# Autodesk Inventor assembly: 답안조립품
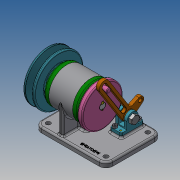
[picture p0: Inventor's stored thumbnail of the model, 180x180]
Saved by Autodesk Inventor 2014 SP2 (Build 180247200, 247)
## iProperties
Created: 2019-09
Part Number: 답안조립품
Document SubType Name: Assembly
Designer: kb542
Mass: 1417.85 g
Surface Area: 1426.65 cm^2
Volume: 427.118 cm^3
Density: 3.31959 g/cm^3
Author: kb542
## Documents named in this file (19)
- C:\Users\kb542\Desktop\390904V1007\답안조립품.iam
- C:\Users\kb542\Desktop\390904V1007\본체.ipt
- C:\Users\kb542\Desktop\390904V1007\V-벨트풀리.ipt
- C:\Users\kb542\Desktop\390904V1007\너트 M8.ipt
- C:\Users\kb542\Desktop\390904V1007\너트 M10x1.ipt
- C:\Users\kb542\Desktop\390904V1007\돌림판.ipt
- C:\Users\kb542\Desktop\390904V1007\멈춤나사 M3x5.ipt
- C:\Users\kb542\Desktop\390904V1007\베어링 6004.ipt
- C:\Users\kb542\Desktop\390904V1007\볼트 M4.ipt
- C:\Users\kb542\Desktop\390904V1007\오일 실 17 30 5.ipt
- C:\Users\kb542\Desktop\390904V1007\와셔 8x15.5.ipt
- C:\Users\kb542\Desktop\390904V1007\축.ipt
- C:\Users\kb542\Desktop\390904V1007\커버.ipt
- C:\Users\kb542\Desktop\390904V1007\크랭크.ipt
- C:\Users\kb542\Desktop\390904V1007\키 4 x 4 x 8.ipt
- C:\Users\kb542\Desktop\390904V1007\키 5 x 5 x 12.ipt
- C:\Users\kb542\Desktop\390904V1007\핀 3 x 8.ipt
- C:\Users\kb542\Desktop\390904V1007\힌지 축.ipt
- C:\Users\kb542\Desktop\390904V1007\힌지.ipt
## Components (3 placed, 2 different names)
1. V-벨트풀리:1 — 각도:4
2. 핀 3 x 8:1
3. 핀 3 x 8:2
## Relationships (1: Angle 1)
- 각도:4 [Angle]: V-벨트풀리:1
